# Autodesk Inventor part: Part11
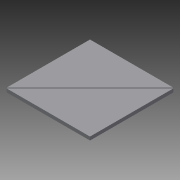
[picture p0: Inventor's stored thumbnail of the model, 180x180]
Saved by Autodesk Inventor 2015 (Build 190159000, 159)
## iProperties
Created: 2015-04
Part Number: Part11
Material: Generic
Document SubType Name: Modeling
Designer: TREINA5
Density: 1 g/cm^3
Appearance: Default
Mass: 128924 g
Surface Area: 48980.5 cm^2
Volume: 128924 cm^3
Author: TREINA5
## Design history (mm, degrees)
sketch "Sketch1"
  geometry: L1 (8980, 5965.824)-(8980, 4499.966); L2 (7514.142, 4499.966)-(8980, 4499.966); L3 (8980, 5965.824)-(7514.142, 4499.966); L4 (7500, 4514.109)-(7500, 5979.966); L5 (8965.858, 5979.966)-(7499.81, 4513.918); L6 (7500, 5979.966)-(8965.858, 5979.966); A1 r 1510 centre (5990, 4489.966) between (7499.966, 4479.933) and (7499.966, 4479.966); 1 further point
  constraints: 12 end point, 2 point on circle, 1 centre point, 1 point on line
extrude "Extrusion1" new body sketch "Sketch1" distance "d0" = 60; taper "d1" = 0 deg
extrude "Extrusion2" new body sketch "Sketch1" distance "d2" = 60; taper "d3" = 0 deg
body "Solid1"
body "Solid2"
